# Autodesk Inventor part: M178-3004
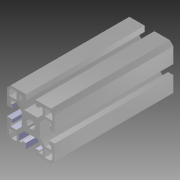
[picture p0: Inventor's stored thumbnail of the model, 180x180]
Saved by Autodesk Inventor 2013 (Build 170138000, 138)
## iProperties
Created: 2004-10
Material: Aluminium - 6061
Document SubType Name: Modeling
Designer: Autodesk, Inc.
Manufacturer: Standard
Standards Organization: Custom
Description: HUTCH, OVERHANG, GUSSET BAR
Stock Number: 10-040
Catalog Web Link: http://www.parker.com/ead/cm1.asp?cmid=809
Vendor: PARKER IPS
Part Number: M178-3004
Mass: 179.948 g
Surface Area: 483.565 cm^2
Volume: 66.4013 cm^3
Density: 2.71 g/cm^3
CAGE: 1LJX3
Dept. ID: Product Design
Description #2: ---
Finish #1: ---
Finish #2: ---
Material ID: ---
Project Number: ---
Length: 304.800 mm
Author: Autodesk, Inc.
Revision Number: A
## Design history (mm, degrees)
derived "40 Series Profiles.ipt"
sketch "Sketch1"
  geometry: L1 (0, -24)-(-304.8, -24) reference; L2 (0, 16)-(-304.8, 16) reference; L3 (-304.8, 13)-(-304.8, 0) reference; L4 (-264.8, 16)-(-304.8, -24); L5 (-304.8, -24)-(-304.8, 16); L6 (-304.8, 16)-(-264.8, 16)
  constraints: 6 end point, 3 collinear, 1 perpendicular, 1 point on line
  dimensions: "d3" = 45 deg angle of L4 L2
extrude "Extrusion1" cut sketch "Sketch1" stored distance "d1" = 10; taper "d2" = 0 deg
mirror "Mirror1"
workplane "Work Plane1"
sketch "Sketch2"
  geometry: L1 (13, 0)-(0, 0) reference; L2 (13, 56.569)-(13, 215.526) reference; L3 (21, 215.526)-(21, 56.569) reference; L4 (13, 56.569)-(21, 56.569); L5 (17, 56.569)-(17, 37.3); C1 r 4.5 at (17, 37.3); C2 r 7.5 at (17, 37.3)
  constraints: 4 end point, 2 centre point, 2 coincident, 2 perpendicular, 1 midpoint
  dimensions: "d5" = 9 diameter of C1; "d6" = 15 diameter of C2; "d7" = 37.3 distance from line of L5.end L1
extrude "Extrusion2" cut sketch "Sketch2" stored distance "d8" = 10; taper "d9" = 0 deg
extrude "Extrusion3" cut sketch "Sketch2" stored distance "d10" = 10; taper "d11" = 0 deg
mirror "Mirror2"
body "Solid1"
tag "TaggingFeature2"
feature "Solid1::40 Series Profiles.ipt" dims "ScaleForDerivedMember" = 10
other parameters: "Length" = 304.8, "d4" = -9
